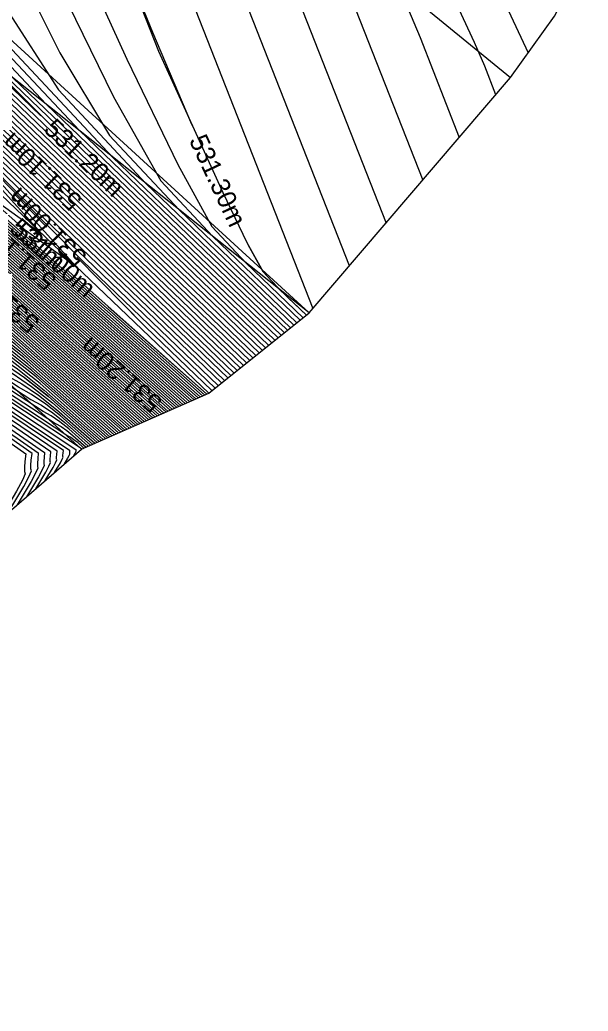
# Model space of a CAD drawing. Extents: x -866683 to -866410, y -1041951 to -1040252.
# Drawn here: x -866431.19 to -866422.11, y -1041936.26 to -1041920.43 of the extents above; entities that cross this region are included whole.
import ezdxf

# ---------------------------------------------------------------- set-up
doc = ezdxf.new("R2010")
doc.units = 0
for name, color, linetype in [('BODY', 7, 'Continuous'), ('BODY_2016', 7, 'Continuous'), ('BREAKLINE', 7, 'Continuous'), ('EXTERIOR', 7, 'Continuous'), ('V-HL', 7, 'Continuous'), ('V-POPIS', 7, 'Continuous'), ('V-VEDL', 7, 'Continuous'), ('V_po_cm', 7, 'Continuous')]:
    doc.layers.add(name, color=color, linetype=linetype)

msp = doc.modelspace()

# ---------------------------------------------------------------- linework, layer by layer
at = {"layer": 'BREAKLINE'}
for points in [[(-866470.416, -1041813.512), (-866469.678, -1041818.801), (-866468.328, -1041828.98), (-866464.804, -1041855.208), (-866460.868, -1041884.031), (-866456.109, -1041894.798), (-866454.046, -1041896.659), (-866450.549, -1041899.657), (-866442.256, -1041905.958), (-866433.526, -1041913.041), (-866423.347, -1041921.351)], [(-866451.679, -1041950.508), (-866455.618, -1041922.473), (-866456.719, -1041912.396), (-866455.207, -1041909.853), (-866453.752, -1041908.342), (-866450, -1041907.538), (-866447.7, -1041908.076), (-866445.165, -1041909.459), (-866437.422, -1041915.176), (-866426.565, -1041925.108), (-866438.22, -1041915.868), (-866445.312, -1041910.554), (-866447.7, -1041908.076)], [(-866445.626, -1041911.77), (-866438.844, -1041916.202), (-866428.169, -1041926.387)], [(-866430.202, -1041927.282), (-866445.247, -1041913.64), (-866449.543, -1041926.354), (-866449.641, -1041934.033), (-866450.183, -1041936.864), (-866452.267, -1041937.851), (-866451.576, -1041945.087)]]:
    msp.add_lwpolyline(points, dxfattribs=at)
at = {"layer": 'EXTERIOR'}
msp.add_lwpolyline([(-866470.107, -1041899.606), (-866467.474, -1041915.319), (-866464.952, -1041936.638), (-866464.966, -1041937.083), (-866464.745, -1041941.128), (-866464.731, -1041942.196), (-866464.769, -1041945.786), (-866461.426, -1041946.157), (-866460.329, -1041945.918), (-866459.426, -1041945.724), (-866458.763, -1041945.697), (-866451.679, -1041950.508), (-866451.576, -1041945.087), (-866450.598, -1041944.936), (-866430.202, -1041927.282), (-866428.169, -1041926.387), (-866426.565, -1041925.108), (-866423.347, -1041921.351), (-866422.644, -1041920.368), (-866422.16, -1041919.445), (-866422.107, -1041897.411)], dxfattribs=at)
at = {"layer": 'V-HL'}
for points in [[(-866430.757, -1041923.737), (-866431.285, -1041923.204)], [(-866429.174, -1041925.335), (-866430.278, -1041924.22)], [(-866428.203, -1041926.402), (-866430.448, -1041924.412)], [(-866429.174, -1041925.335), (-866428.119, -1041926.347)]]:
    msp.add_lwpolyline(points, dxfattribs=at)
at = {"layer": 'V-VEDL'}
for points in [[(-866449.659, -1041913.644), (-866448.578, -1041915.389), (-866447.726, -1041916.519), (-866447.105, -1041917.032), (-866446.714, -1041916.929), (-866444.683, -1041918.021), (-866441.012, -1041920.308), (-866435.701, -1041923.791), (-866432.161, -1041926.121), (-866430.392, -1041927.299), (-866430.395, -1041927.324), (-866430.397, -1041927.344), (-866430.396, -1041927.358), (-866430.395, -1041927.366), (-866430.404, -1041927.388), (-866430.424, -1041927.425), (-866430.486, -1041927.528)], [(-866431.599, -1041914.338), (-866431.459, -1041914.636), (-866431.145, -1041915.418), (-866430.585, -1041916.834), (-866428.975, -1041920.931)], [(-866427.616, -1041925.946), (-866434.331, -1041919.509), (-866436.619, -1041917.309), (-866437.84, -1041916.128), (-866437.992, -1041915.965), (-866438.251, -1041915.753), (-866438.616, -1041915.49), (-866439.558, -1041914.865)], [(-866441.671, -1041916.883), (-866437.725, -1041919.072), (-866435.609, -1041920.511), (-866433.35, -1041922.296), (-866428.547, -1041926.554)], [(-866427.113, -1041925.545), (-866430.615, -1041922.188), (-866432.301, -1041920.515), (-866433.923, -1041918.849)], [(-866439.286, -1041919.045), (-866436.161, -1041920.779), (-866434.485, -1041921.919), (-866432.696, -1041923.332), (-866428.891, -1041926.705)], [(-866428.975, -1041920.931), (-866427.945, -1041923.188), (-866427.559, -1041923.986), (-866427.301, -1041924.454), (-866427.173, -1041924.591), (-866427.039, -1041924.729), (-866426.899, -1041924.867), (-866426.61, -1041925.144)], [(-866436.902, -1041921.207), (-866434.597, -1041922.486), (-866433.361, -1041923.327), (-866432.041, -1041924.369), (-866429.235, -1041926.856)], [(-866429.579, -1041927.008), (-866431.387, -1041925.406), (-866432.237, -1041924.734), (-866433.033, -1041924.193), (-866434.518, -1041923.369)], [(-866429.923, -1041927.159), (-866430.732, -1041926.442), (-866431.113, -1041926.142), (-866431.469, -1041925.899), (-866432.133, -1041925.531)]]:
    msp.add_lwpolyline(points, dxfattribs=at)
at = {"layer": 'V_po_cm'}
for points in [[(-866441.939, -1041911.841), (-866441.165, -1041909.798), (-866440.116, -1041909.599), (-866438.405, -1041910.223), (-866436.033, -1041911.669), (-866433.972, -1041913.682), (-866432.224, -1041916.263), (-866430.788, -1041919.411), (-866429.692, -1041921.657), (-866428.937, -1041923.001), (-866428.108, -1041923.884)], [(-866441.401, -1041912.238), (-866440.719, -1041910.438), (-866439.795, -1041910.263), (-866438.288, -1041910.812), (-866436.198, -1041912.086), (-866434.383, -1041913.86), (-866432.843, -1041916.133), (-866431.577, -1041918.907), (-866430.548, -1041920.954), (-866429.755, -1041922.274), (-866428.641, -1041923.463)], [(-866440.863, -1041912.635), (-866440.274, -1041911.079), (-866439.475, -1041910.927), (-866438.171, -1041911.402), (-866436.364, -1041912.504), (-866434.794, -1041914.038), (-866433.462, -1041916.004), (-866432.367, -1041918.403), (-866431.404, -1041920.25), (-866430.573, -1041921.548), (-866429.173, -1041923.041)], [(-866429.705, -1041922.619), (-866431.391, -1041920.821), (-866432.261, -1041919.547), (-866433.157, -1041917.898), (-866434.08, -1041915.875), (-866435.204, -1041914.216), (-866436.529, -1041912.921), (-866438.054, -1041911.992), (-866439.154, -1041911.591), (-866439.828, -1041911.719), (-866440.326, -1041913.032)], [(-866439.788, -1041913.429), (-866439.383, -1041912.359), (-866438.833, -1041912.255), (-866437.937, -1041912.581), (-866436.694, -1041913.339), (-866435.615, -1041914.393), (-866434.699, -1041915.745), (-866433.947, -1041917.394), (-866433.117, -1041918.844), (-866432.209, -1041920.094), (-866430.237, -1041922.197)], [(-866449.481, -1041912.566), (-866449.048, -1041913.644), (-866448.116, -1041915.147), (-866447.383, -1041916.12), (-866446.848, -1041916.562), (-866446.511, -1041916.473), (-866444.7, -1041917.455), (-866441.415, -1041919.505), (-866436.655, -1041922.626), (-866433.384, -1041924.761), (-866431.604, -1041925.909), (-866431.312, -1041926.07), (-866431, -1041926.283), (-866430.667, -1041926.546), (-866429.958, -1041927.174)], [(-866449.33, -1041912.604), (-866448.912, -1041913.643), (-866448.014, -1041915.093), (-866447.307, -1041916.031), (-866446.791, -1041916.458), (-866446.466, -1041916.372), (-866444.72, -1041917.318), (-866441.551, -1041919.296), (-866436.962, -1041922.305), (-866433.777, -1041924.381), (-866431.998, -1041925.522), (-866431.625, -1041925.729), (-866431.225, -1041926.001), (-866430.798, -1041926.339), (-866429.889, -1041927.144)], [(-866429.855, -1041927.129), (-866430.863, -1041926.235), (-866431.337, -1041925.86), (-866431.782, -1041925.558), (-866432.196, -1041925.328), (-866433.974, -1041924.191), (-866437.115, -1041922.145), (-866441.62, -1041919.191), (-866444.729, -1041917.25), (-866446.444, -1041916.322), (-866446.762, -1041916.406), (-866447.269, -1041915.987), (-866447.963, -1041915.066), (-866448.844, -1041913.643), (-866449.254, -1041912.623)], [(-866429.82, -1041927.114), (-866430.929, -1041926.131), (-866431.45, -1041925.72), (-866431.938, -1041925.387), (-866432.393, -1041925.135), (-866434.17, -1041924), (-866437.268, -1041921.984), (-866441.688, -1041919.087), (-866444.739, -1041917.182), (-866446.421, -1041916.271), (-866446.734, -1041916.353), (-866447.231, -1041915.943), (-866447.911, -1041915.04), (-866448.776, -1041913.643), (-866449.179, -1041912.643)], [(-866439.25, -1041913.826), (-866438.937, -1041912.999), (-866438.512, -1041912.919), (-866437.82, -1041913.171), (-866436.86, -1041913.756), (-866436.026, -1041914.571), (-866435.318, -1041915.616), (-866434.737, -1041916.89), (-866433.973, -1041918.141), (-866433.027, -1041919.368), (-866430.769, -1041921.775)], [(-866432.733, -1041913.575), (-866432.675, -1041913.698), (-866432.545, -1041914.02), (-866432.315, -1041914.603), (-866431.983, -1041915.446), (-866431.4, -1041916.803), (-866430.565, -1041918.673), (-866429.478, -1041921.055), (-866428.662, -1041922.74), (-866428.119, -1041923.727), (-866427.576, -1041924.306)], [(-866450.134, -1041913.645), (-866448.936, -1041915.578), (-866447.993, -1041916.829), (-866447.306, -1041917.397), (-866446.872, -1041917.283), (-866444.877, -1041918.326), (-866441.319, -1041920.526), (-866436.199, -1041923.883), (-866432.79, -1041926.161), (-866431.093, -1041927.36), (-866431.106, -1041927.481), (-866431.113, -1041927.573), (-866431.113, -1041927.638), (-866431.105, -1041927.675), (-866431.148, -1041927.779), (-866431.242, -1041927.952), (-866431.531, -1041928.432)], [(-866431.382, -1041928.303), (-866431.125, -1041927.877), (-866431.042, -1041927.724), (-866431.004, -1041927.631), (-866431.01, -1041927.598), (-866431.011, -1041927.54), (-866431.005, -1041927.458), (-866430.993, -1041927.351), (-866432.7, -1041926.155), (-866436.128, -1041923.87), (-866441.275, -1041920.495), (-866444.849, -1041918.282), (-866446.85, -1041917.232), (-866447.277, -1041917.345), (-866447.955, -1041916.784), (-866448.885, -1041915.551), (-866450.066, -1041913.645)], [(-866449.998, -1041913.644), (-866448.834, -1041915.524), (-866447.917, -1041916.74), (-866447.248, -1041917.293), (-866446.827, -1041917.182), (-866444.822, -1041918.239), (-866441.231, -1041920.464), (-866436.057, -1041923.857), (-866432.61, -1041926.15), (-866430.893, -1041927.343), (-866430.903, -1041927.436), (-866430.908, -1041927.508), (-866430.908, -1041927.558), (-866430.902, -1041927.586), (-866430.936, -1041927.668), (-866431.008, -1041927.801), (-866431.232, -1041928.174)], [(-866449.93, -1041913.644), (-866448.782, -1041915.497), (-866447.879, -1041916.696), (-866447.22, -1041917.24), (-866446.805, -1041917.131), (-866444.794, -1041918.195), (-866441.188, -1041920.433), (-866435.985, -1041923.843), (-866432.52, -1041926.144), (-866430.792, -1041927.334), (-866430.802, -1041927.414), (-866430.806, -1041927.475), (-866430.806, -1041927.518), (-866430.801, -1041927.542), (-866430.829, -1041927.612), (-866430.892, -1041927.726), (-866431.083, -1041928.045)], [(-866430.934, -1041927.915), (-866430.775, -1041927.651), (-866430.723, -1041927.556), (-866430.699, -1041927.498), (-866430.703, -1041927.478), (-866430.704, -1041927.442), (-866430.7, -1041927.391), (-866430.692, -1041927.325), (-866432.43, -1041926.138), (-866435.914, -1041923.83), (-866441.144, -1041920.402), (-866444.766, -1041918.152), (-866446.782, -1041917.081), (-866447.191, -1041917.188), (-866447.841, -1041916.651), (-866448.731, -1041915.47), (-866449.862, -1041913.644)], [(-866430.784, -1041927.786), (-866430.658, -1041927.576), (-866430.617, -1041927.5), (-866430.598, -1041927.454), (-866430.601, -1041927.438), (-866430.601, -1041927.41), (-866430.598, -1041927.369), (-866430.592, -1041927.316), (-866432.341, -1041926.132), (-866435.843, -1041923.817), (-866441.1, -1041920.37), (-866444.739, -1041918.108), (-866446.76, -1041917.03), (-866447.163, -1041917.136), (-866447.803, -1041916.607), (-866448.68, -1041915.443), (-866449.795, -1041913.644)], [(-866430.635, -1041927.657), (-866430.541, -1041927.5), (-866430.51, -1041927.444), (-866430.496, -1041927.41), (-866430.499, -1041927.398), (-866430.499, -1041927.377), (-866430.497, -1041927.347), (-866430.492, -1041927.307), (-866432.251, -1041926.127), (-866435.772, -1041923.804), (-866441.056, -1041920.339), (-866444.711, -1041918.065), (-866446.737, -1041916.979), (-866447.134, -1041917.084), (-866447.765, -1041916.563), (-866448.629, -1041915.416), (-866449.727, -1041913.644)], [(-866449.591, -1041913.644), (-866448.526, -1041915.362), (-866447.688, -1041916.474), (-866447.077, -1041916.98), (-866446.692, -1041916.878), (-866444.656, -1041917.977), (-866440.968, -1041920.277), (-866435.629, -1041923.777), (-866432.071, -1041926.115), (-866430.292, -1041927.29), (-866430.293, -1041927.302), (-866430.294, -1041927.311), (-866430.294, -1041927.318), (-866430.293, -1041927.322), (-866430.298, -1041927.332), (-866430.307, -1041927.35), (-866430.336, -1041927.398)], [(-866430.199, -1041927.28), (-866430.209, -1041927.272), (-866430.213, -1041927.268), (-866430.218, -1041927.265), (-866430.222, -1041927.263), (-866432.009, -1041926.091), (-866435.581, -1041923.75), (-866440.936, -1041920.239), (-866444.632, -1041917.931), (-866446.669, -1041916.828), (-866447.048, -1041916.927), (-866447.65, -1041916.43), (-866448.475, -1041915.336), (-866449.523, -1041913.644)], [(-866449.455, -1041913.644), (-866448.424, -1041915.309), (-866447.612, -1041916.386), (-866447.02, -1041916.875), (-866446.647, -1041916.777), (-866444.641, -1041917.863), (-866441.004, -1041920.134), (-866435.734, -1041923.589), (-866432.206, -1041925.901), (-866430.419, -1041927.069), (-866430.374, -1041927.094), (-866430.326, -1041927.127), (-866430.274, -1041927.168), (-866430.164, -1041927.265)], [(-866449.387, -1041913.644), (-866448.373, -1041915.282), (-866447.574, -1041916.341), (-866446.991, -1041916.823), (-866446.624, -1041916.726), (-866444.651, -1041917.795), (-866441.072, -1041920.029), (-866435.888, -1041923.429), (-866432.402, -1041925.711), (-866430.617, -1041926.876), (-866430.53, -1041926.924), (-866430.438, -1041926.986), (-866430.339, -1041927.064), (-866430.13, -1041927.25)], [(-866430.095, -1041927.235), (-866430.405, -1041926.961), (-866430.55, -1041926.846), (-866430.687, -1041926.753), (-866430.814, -1041926.682), (-866432.599, -1041925.521), (-866436.041, -1041923.268), (-866441.141, -1041919.924), (-866444.661, -1041917.727), (-866446.602, -1041916.676), (-866446.962, -1041916.771), (-866447.536, -1041916.297), (-866448.321, -1041915.255), (-866449.319, -1041913.644)], [(-866449.252, -1041913.644), (-866448.27, -1041915.228), (-866447.498, -1041916.253), (-866446.934, -1041916.719), (-866446.579, -1041916.625), (-866444.671, -1041917.659), (-866441.209, -1041919.82), (-866436.194, -1041923.108), (-866432.795, -1041925.331), (-866431.011, -1041926.489), (-866430.843, -1041926.582), (-866430.663, -1041926.705), (-866430.47, -1041926.857), (-866430.061, -1041927.22)], [(-866430.027, -1041927.205), (-866430.536, -1041926.753), (-866430.775, -1041926.564), (-866431, -1041926.412), (-866431.209, -1041926.295), (-866432.992, -1041925.141), (-866436.348, -1041922.947), (-866441.278, -1041919.715), (-866444.681, -1041917.591), (-866446.556, -1041916.575), (-866446.905, -1041916.666), (-866447.459, -1041916.209), (-866448.219, -1041915.201), (-866449.184, -1041913.644)], [(-866449.116, -1041913.644), (-866448.168, -1041915.174), (-866447.421, -1041916.164), (-866446.877, -1041916.614), (-866446.534, -1041916.524), (-866444.69, -1041917.523), (-866441.346, -1041919.61), (-866436.501, -1041922.787), (-866433.188, -1041924.951), (-866431.406, -1041926.102), (-866431.156, -1041926.241), (-866430.888, -1041926.423), (-866430.601, -1041926.65), (-866429.992, -1041927.19)], [(-866430.465, -1041915.102), (-866430.244, -1041915.575), (-866429.767, -1041916.758), (-866428.924, -1041918.887), (-866426.506, -1041925.04)], [(-866427.666, -1041925.986), (-866438.22, -1041915.868)], [(-866425.921, -1041924.357), (-866427.891, -1041919.343), (-866428.599, -1041917.564), (-866429.028, -1041916.513), (-866429.332, -1041915.865)], [(-866437.156, -1041916.712), (-866427.566, -1041925.906)], [(-866428.198, -1041916.628), (-866427.813, -1041917.451), (-866427.43, -1041918.371), (-866426.859, -1041919.8), (-866425.336, -1041923.674)], [(-866427.716, -1041926.026), (-866437.215, -1041916.92)], [(-866427.515, -1041925.866), (-866436.623, -1041917.134)], [(-866427.065, -1041917.391), (-866426.597, -1041918.39), (-866426.262, -1041919.178), (-866425.826, -1041920.256), (-866424.751, -1041922.99)], [(-866427.465, -1041925.826), (-866436.091, -1041917.556)], [(-866427.767, -1041926.066), (-866436.21, -1041917.972)], [(-866427.415, -1041925.786), (-866435.559, -1041917.978)], [(-866429.511, -1041926.978), (-866431.518, -1041925.198), (-866432.461, -1041924.453), (-866433.346, -1041923.851), (-866434.17, -1041923.394), (-866435.938, -1041922.29), (-866438.649, -1041920.54), (-866442.304, -1041918.144)], [(-866425.931, -1041918.155), (-866425.381, -1041919.328), (-866425.094, -1041919.985), (-866424.793, -1041920.712), (-866424.166, -1041922.307)], [(-866429.545, -1041926.993), (-866431.452, -1041925.302), (-866432.349, -1041924.593), (-866433.189, -1041924.022), (-866433.973, -1041923.587), (-866435.742, -1041922.48), (-866438.496, -1041920.701), (-866442.236, -1041918.249)], [(-866430.034, -1041918.235), (-866429.78, -1041918.882), (-866429.071, -1041920.624), (-866428.46, -1041922.06), (-866428.433, -1041922.118)], [(-866429.614, -1041927.023), (-866431.321, -1041925.509), (-866432.124, -1041924.875), (-866432.876, -1041924.363), (-866433.578, -1041923.974), (-866435.349, -1041922.86), (-866438.189, -1041921.022), (-866442.099, -1041918.458)], [(-866435.988, -1041918.383), (-866431.184, -1041923.231)], [(-866427.364, -1041925.745), (-866435.027, -1041918.4)], [(-866429.648, -1041927.038), (-866431.256, -1041925.613), (-866432.012, -1041925.016), (-866432.72, -1041924.534), (-866433.38, -1041924.168), (-866435.152, -1041923.05), (-866438.036, -1041921.182), (-866442.031, -1041918.563)], [(-866441.962, -1041918.668), (-866437.882, -1041921.342), (-866434.956, -1041923.24), (-866433.183, -1041924.361), (-866432.564, -1041924.705), (-866431.899, -1041925.156), (-866431.19, -1041925.717), (-866429.683, -1041927.053)], [(-866429.717, -1041927.068), (-866431.125, -1041925.82), (-866431.787, -1041925.297), (-866432.407, -1041924.875), (-866432.986, -1041924.554), (-866434.759, -1041923.43), (-866437.729, -1041921.503), (-866441.894, -1041918.772)], [(-866437.037, -1041918.752), (-866434.372, -1041920.842), (-866431.609, -1041923.292), (-866430.837, -1041923.844), (-866432.058, -1041922.498), (-866435.272, -1041919.254)], [(-866435.669, -1041918.742), (-866430.179, -1041924.283)], [(-866429.751, -1041927.084), (-866431.059, -1041925.924), (-866431.675, -1041925.438), (-866432.251, -1041925.046), (-866432.788, -1041924.748), (-866434.563, -1041923.62), (-866437.575, -1041921.663), (-866441.825, -1041918.877)], [(-866436.845, -1041918.963), (-866434.07, -1041921.155), (-866431.12, -1041923.771), (-866430.296, -1041924.361), (-866431.6, -1041922.924), (-866435.031, -1041919.461)], [(-866427.314, -1041925.705), (-866434.495, -1041918.821)], [(-866423.581, -1041921.624), (-866423.76, -1041921.168), (-866423.925, -1041920.792), (-866424.166, -1041920.266), (-866424.798, -1041918.918)], [(-866429.786, -1041927.099), (-866430.994, -1041926.028), (-866431.562, -1041925.579), (-866432.094, -1041925.217), (-866432.591, -1041924.941), (-866434.367, -1041923.81), (-866437.422, -1041921.824), (-866441.757, -1041918.982)], [(-866429.201, -1041926.841), (-866432.107, -1041924.265), (-866433.473, -1041923.186), (-866434.753, -1041922.315), (-866435.947, -1041921.653), (-866437.706, -1041920.58), (-866440.03, -1041919.096)], [(-866427.817, -1041926.106), (-866435.205, -1041919.024)], [(-866437.568, -1041919.243), (-866435.497, -1041920.652), (-866433.285, -1041922.399), (-866428.582, -1041926.569)], [(-866428.238, -1041926.417), (-866433.939, -1041921.363), (-866436.621, -1041919.245)], [(-866433.962, -1041919.243), (-866427.264, -1041925.665)], [(-866439.723, -1041919.417), (-866437.313, -1041920.96), (-866435.552, -1041922.04), (-866434.44, -1041922.656), (-866433.248, -1041923.467), (-866431.976, -1041924.473), (-866429.27, -1041926.872)], [(-866438.884, -1041919.44), (-866437.131, -1041920.492), (-866435.692, -1041921.291), (-866434.148, -1041922.341), (-866432.499, -1041923.643), (-866428.995, -1041926.75)], [(-866437.412, -1041919.413), (-866435.384, -1041920.793), (-866433.219, -1041922.503), (-866428.616, -1041926.584)], [(-866428.272, -1041926.432), (-866433.874, -1041921.466), (-866436.508, -1041919.385)], [(-866429.304, -1041926.887), (-866431.91, -1041924.576), (-866433.136, -1041923.608), (-866434.284, -1041922.827), (-866435.355, -1041922.233), (-866437.117, -1041921.15), (-866439.57, -1041919.577)], [(-866438.118, -1041919.525), (-866436.474, -1041920.437), (-866434.71, -1041921.637), (-866432.827, -1041923.125), (-866428.823, -1041926.675)], [(-866428.651, -1041926.599), (-866433.154, -1041922.607), (-866435.272, -1041920.934), (-866437.256, -1041919.584)], [(-866428.307, -1041926.448), (-866433.809, -1041921.57), (-866436.396, -1041919.526)], [(-866429.339, -1041926.902), (-866431.845, -1041924.68), (-866433.024, -1041923.749), (-866434.128, -1041922.998), (-866435.157, -1041922.427), (-866436.92, -1041921.34), (-866439.417, -1041919.738)], [(-866438.688, -1041919.63), (-866436.934, -1041920.686), (-866435.535, -1041921.462), (-866434.035, -1041922.482), (-866432.434, -1041923.747), (-866429.029, -1041926.766)], [(-866437.921, -1041919.718), (-866436.317, -1041920.608), (-866434.597, -1041921.778), (-866432.761, -1041923.229), (-866428.857, -1041926.69)], [(-866428.685, -1041926.614), (-866433.089, -1041922.71), (-866435.159, -1041921.074), (-866437.099, -1041919.755)], [(-866428.341, -1041926.463), (-866433.743, -1041921.674), (-866436.283, -1041919.667)], [(-866427.214, -1041925.625), (-866433.43, -1041919.665)], [(-866423.664, -1041919.681), (-866423.066, -1041920.958)], [(-866429.373, -1041926.917), (-866431.779, -1041924.784), (-866432.911, -1041923.89), (-866433.971, -1041923.168), (-866434.96, -1041922.62), (-866436.724, -1041921.53), (-866439.263, -1041919.898)], [(-866438.491, -1041919.82), (-866436.736, -1041920.879), (-866435.379, -1041921.632), (-866433.923, -1041922.623), (-866432.369, -1041923.851), (-866429.063, -1041926.781)], [(-866428.375, -1041926.478), (-866433.678, -1041921.777), (-866436.171, -1041919.808)], [(-866429.407, -1041926.932), (-866431.714, -1041924.887), (-866432.799, -1041924.03), (-866433.815, -1041923.339), (-866434.762, -1041922.814), (-866436.527, -1041921.72), (-866439.11, -1041920.059)], [(-866438.295, -1041920.01), (-866436.539, -1041921.073), (-866435.222, -1041921.803), (-866433.81, -1041922.764), (-866432.303, -1041923.954), (-866429.098, -1041926.796)], [(-866428.719, -1041926.629), (-866433.023, -1041922.814), (-866435.047, -1041921.215), (-866436.943, -1041919.925)], [(-866428.41, -1041926.493), (-866433.612, -1041921.881), (-866436.059, -1041919.948)], [(-866438.956, -1041920.219), (-866436.331, -1041921.91), (-866434.565, -1041923.007), (-866433.658, -1041923.51), (-866432.686, -1041924.171), (-866431.649, -1041924.991), (-866429.442, -1041926.947)], [(-866429.132, -1041926.811), (-866432.238, -1041924.058), (-866433.698, -1041922.904), (-866435.066, -1041921.974), (-866436.342, -1041921.266), (-866438.099, -1041920.2)], [(-866437.526, -1041920.105), (-866436.004, -1041920.95), (-866434.372, -1041922.06), (-866432.63, -1041923.436), (-866428.926, -1041926.72)], [(-866436.786, -1041920.096), (-866434.934, -1041921.356), (-866432.958, -1041922.918), (-866428.754, -1041926.644)], [(-866428.444, -1041926.508), (-866433.547, -1041921.985), (-866435.946, -1041920.089)], [(-866428.479, -1041926.523), (-866433.481, -1041922.088), (-866435.834, -1041920.23)], [(-866427.867, -1041926.146), (-866434.2, -1041920.076)], [(-866427.163, -1041925.585), (-866432.898, -1041920.087)], [(-866429.476, -1041926.962), (-866431.583, -1041925.095), (-866432.574, -1041924.312), (-866433.502, -1041923.681), (-866434.367, -1041923.2), (-866436.134, -1041922.1), (-866438.803, -1041920.38)], [(-866437.902, -1041920.39), (-866436.144, -1041921.459), (-866434.91, -1041922.144), (-866433.586, -1041923.045), (-866432.172, -1041924.162), (-866429.167, -1041926.826)], [(-866428.96, -1041926.735), (-866432.565, -1041923.54), (-866434.26, -1041922.201), (-866435.848, -1041921.12), (-866437.329, -1041920.299)], [(-866428.788, -1041926.66), (-866432.892, -1041923.021), (-866434.822, -1041921.497), (-866436.63, -1041920.267)], [(-866428.513, -1041926.538), (-866433.416, -1041922.192), (-866435.721, -1041920.371)], [(-866432.366, -1041920.509), (-866430.85, -1041921.962)], [(-866431.834, -1041920.931), (-866427.063, -1041925.505)], [(-866433.194, -1041921.128), (-866427.918, -1041926.187)], [(-866431.302, -1041921.353), (-866427.013, -1041925.465)], [(-866426.962, -1041925.425), (-866430.769, -1041921.775)], [(-866427.968, -1041926.227), (-866432.189, -1041922.179)], [(-866426.912, -1041925.385), (-866430.237, -1041922.197)], [(-866430.427, -1041925.344), (-866432.696, -1041923.332), (-866433.573, -1041922.639)], [(-866429.705, -1041922.619), (-866426.862, -1041925.345)], [(-866429.173, -1041923.041), (-866426.811, -1041925.304)], [(-866431.184, -1041923.231), (-866428.018, -1041926.267)], [(-866427.616, -1041925.946), (-866430.108, -1041923.556)], [(-866427.113, -1041925.545), (-866429.334, -1041923.416)], [(-866428.641, -1041923.463), (-866426.761, -1041925.264)], [(-866426.711, -1041925.224), (-866428.108, -1041923.884)], [(-866427.044, -1041924.728), (-866427.301, -1041924.454), (-866427.541, -1041924.019)], [(-866430.179, -1041924.283), (-866428.068, -1041926.307)], [(-866426.661, -1041925.184), (-866427.576, -1041924.306)], [(-866428.547, -1041926.554), (-866430.503, -1041924.82)], [(-866427.044, -1041924.728), (-866426.61, -1041925.144)], [(-866429.174, -1041925.335), (-866429.644, -1041924.861)], [(-866428.203, -1041926.402), (-866429.775, -1041925.009)], [(-866429.174, -1041925.335), (-866428.119, -1041926.347)], [(-866429.235, -1041926.856), (-866430.807, -1041925.463)], [(-866429.579, -1041927.008), (-866431.15, -1041925.615)], [(-866432.152, -1041926.126), (-866430.392, -1041927.299), (-866430.395, -1041927.324), (-866430.397, -1041927.344), (-866430.396, -1041927.358), (-866430.395, -1041927.366), (-866430.404, -1041927.388), (-866430.424, -1041927.425), (-866430.486, -1041927.528)], [(-866431.107, -1041926.146), (-866430.732, -1041926.442), (-866429.923, -1041927.159)]]:
    msp.add_lwpolyline(points, dxfattribs=at)

# ---------------------------------------------------------------- texts
at = {"layer": 'BODY'}
for p in [(-866423.347, -1041921.351), (-866426.565, -1041925.108), (-866428.169, -1041926.387), (-866430.202, -1041927.282)]:
    msp.add_text('+', height=0.001, rotation=360, dxfattribs=at).set_placement(p)
at = {"layer": 'BODY_2016'}
for p in [(-866423.347, -1041921.351), (-866426.565, -1041925.108), (-866428.169, -1041926.387), (-866430.202, -1041927.282)]:
    msp.add_text('+', height=0.001, rotation=360, dxfattribs=at).set_placement(p)
at = {"layer": 'V-POPIS'}
msp.add_text('531m', height=0.3, rotation=318.4415, dxfattribs=at).set_placement((-866431.372, -1041923.794))
at = {"layer": 'V_po_cm'}
for s, rotation, p in [('531.20m', 316.2076, (-866430.823, -1041922.196)), ('531.10m', 136.2076, (-866430.172, -1041923.288)), ('531.30m', 295.1469, (-866428.49, -1041922.35)), ('531.00m', 134.7322, (-866430.095, -1041924.193)), ('531.10m', 138.4415, (-866430.577, -1041924.554)), ('531.00m', 318.4415, (-866431.31, -1041923.848)), ('531.30m', 139.1387, (-866430.849, -1041925.228)), ('531.20m', 138.4415, (-866428.891, -1041926.505))]:
    msp.add_text(s, height=0.3, rotation=rotation, dxfattribs=at).set_placement(p)

doc.saveas('drawing.dxf')
